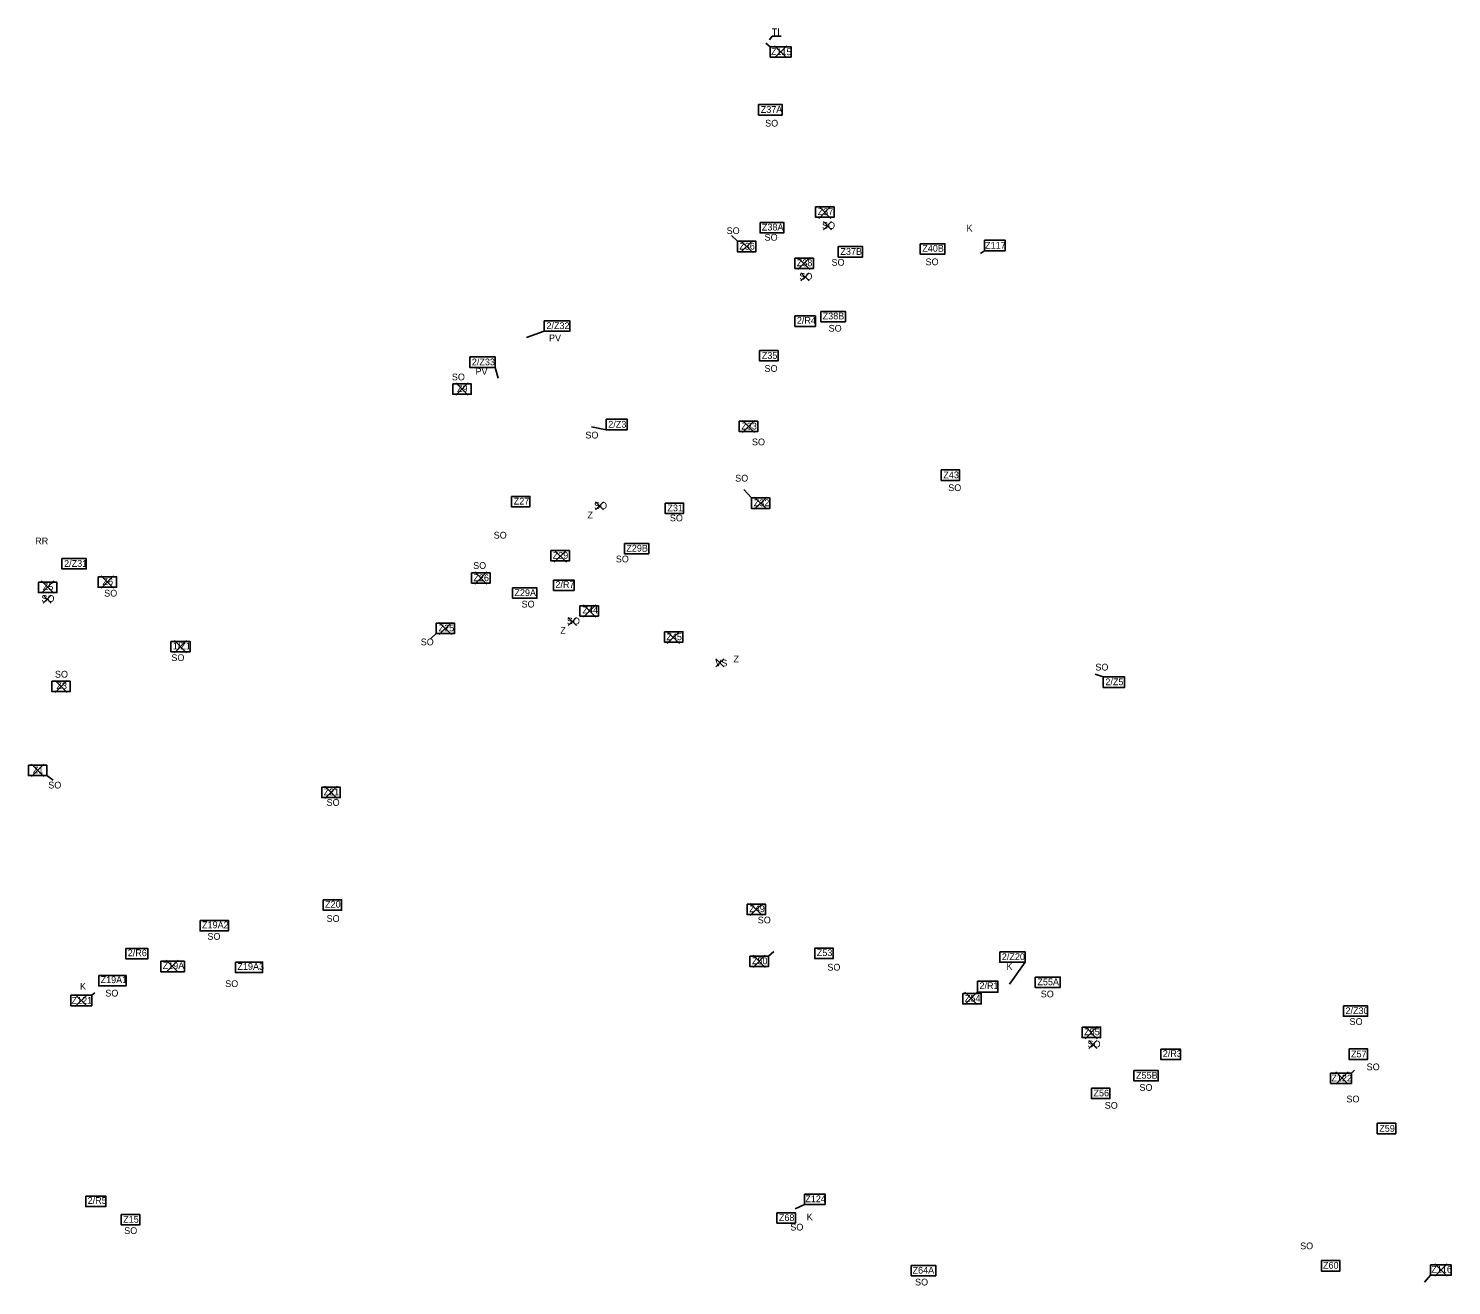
# Model space of a CAD drawing. Extents: x -443466 to -436070, y -1146578 to -1129775.
# Drawn here: x -442879 to -440772, y -1131637 to -1129775 of the extents above; entities that cross this region are included whole.
import ezdxf

# ---------------------------------------------------------------- set-up
doc = ezdxf.new("R2010")
doc.units = 0
for name, color, linetype in [('Vrstva 3', 7, 'Continuous'), ('Vrstva 4', 7, 'Continuous'), ('Vrstva 50', 7, 'Continuous'), ('Vrstva 8', 7, 'Continuous'), ('Vrstva 85', 7, 'Continuous')]:
    doc.layers.add(name, color=color, linetype=linetype)

msp = doc.modelspace()

# ---------------------------------------------------------------- linework, layer by layer
at = {"layer": 'Vrstva 3'}
for p, q in [((-441780.6, -1129802.1), (-441787.2, -1129796.7)), ((-441829.1, -1130090.3), (-441838, -1130081.7)), ((-442115.2, -1130223.5), (-442141.4, -1130232.8)), ((-442187.7, -1130277), (-442183.3, -1130293.2)), ((-442023.6, -1130369.3), (-442045.3, -1130365.1)), ((-441808.5, -1130470.4), (-441819.7, -1130457.7)), ((-442275.3, -1130671.3), (-442283.1, -1130678.3)), ((-441287.6, -1130735.5), (-441299.6, -1130731.1)), ((-442851.5, -1130881.4), (-442842.3, -1130888.4)), ((-441783.2, -1131148.9), (-441775.1, -1131141.9)), ((-441783.2, -1131148.9), (-441775.1, -1131141.9)), ((-441403.2, -1131157.9), (-441426.4, -1131190.3)), ((-440803, -1131621.5), (-440811.7, -1131631.9))]:
    msp.add_line(p, q, dxfattribs=at)
for points in [[(-441780.6, -1129802.1), (-441749.8, -1129802.1), (-441749.8, -1129817.5), (-441780.6, -1129817.5)], [(-441797.8, -1129887.9), (-441762.8, -1129887.9), (-441762.8, -1129903.3), (-441797.8, -1129903.3)], [(-441713.5, -1130039.3), (-441686.2, -1130039.3), (-441686.2, -1130054.7), (-441713.5, -1130054.7)], [(-441795.7, -1130062.4), (-441760.7, -1130062.4), (-441760.7, -1130077.8), (-441795.7, -1130077.8)], [(-441829.1, -1130090.3), (-441801.8, -1130090.3), (-441801.8, -1130105.7), (-441829.1, -1130105.7)], [(-441829.1, -1130090.3), (-441801.8, -1130090.3), (-441801.8, -1130105.7), (-441829.1, -1130105.7)], [(-441829.1, -1130090.3), (-441801.8, -1130090.3), (-441801.8, -1130105.7), (-441829.1, -1130105.7)], [(-441679.8, -1130098.2), (-441643.8, -1130098.2), (-441643.8, -1130113.6), (-441679.8, -1130113.6)], [(-441558.8, -1130093.8), (-441522, -1130093.8), (-441522, -1130109.2), (-441558.8, -1130109.2)], [(-441744, -1130115.3), (-441716.6, -1130115.3), (-441716.6, -1130130.7), (-441744, -1130130.7)], [(-442115.2, -1130208.1), (-442077.3, -1130208.1), (-442077.3, -1130223.5), (-442115.2, -1130223.5)], [(-441744, -1130200.9), (-441713.8, -1130200.9), (-441713.8, -1130216.3), (-441744, -1130216.3)], [(-441705.6, -1130194), (-441669.4, -1130194), (-441669.4, -1130209.4), (-441705.6, -1130209.4)], [(-441796.3, -1130252.1), (-441768.9, -1130252.1), (-441768.9, -1130267.5), (-441796.3, -1130267.5)], [(-442225.5, -1130261.6), (-442187.7, -1130261.6), (-442187.7, -1130277), (-442225.5, -1130277)], [(-442250.7, -1130301.4), (-442223.3, -1130301.4), (-442223.3, -1130316.8), (-442250.7, -1130316.8)], [(-442023.6, -1130353.9), (-441992.3, -1130353.9), (-441992.3, -1130369.3), (-442023.6, -1130369.3)], [(-441826.6, -1130356.8), (-441799.2, -1130356.8), (-441799.2, -1130372.2), (-441826.6, -1130372.2)], [(-441826.6, -1130356.8), (-441799.2, -1130356.8), (-441799.2, -1130372.2), (-441826.6, -1130372.2)], [(-441826.6, -1130356.8), (-441799.2, -1130356.8), (-441799.2, -1130372.2), (-441826.6, -1130372.2)], [(-441527.5, -1130428.9), (-441500.2, -1130428.9), (-441500.2, -1130444.3), (-441527.5, -1130444.3)], [(-441527.5, -1130428.9), (-441500.2, -1130428.9), (-441500.2, -1130444.3), (-441527.5, -1130444.3)], [(-442163.9, -1130468.1), (-442136.5, -1130468.1), (-442136.5, -1130483.5), (-442163.9, -1130483.5)], [(-441936.4, -1130477.9), (-441909, -1130477.9), (-441909, -1130493.3), (-441936.4, -1130493.3)], [(-441808.5, -1130470.4), (-441781.1, -1130470.4), (-441781.1, -1130485.8), (-441808.5, -1130485.8)], [(-442105.4, -1130548.2), (-442078, -1130548.2), (-442078, -1130563.6), (-442105.4, -1130563.6)], [(-442105.4, -1130548.2), (-442078, -1130548.2), (-442078, -1130563.6), (-442105.4, -1130563.6)], [(-442105.4, -1130548.2), (-442078, -1130548.2), (-442078, -1130563.6), (-442105.4, -1130563.6)], [(-441996.3, -1130537.6), (-441960.5, -1130537.6), (-441960.5, -1130553), (-441996.3, -1130553)], [(-442829.3, -1130560.1), (-442793.4, -1130560.1), (-442793.4, -1130575.5), (-442829.3, -1130575.5)], [(-442775.7, -1130587.1), (-442748.3, -1130587.1), (-442748.3, -1130602.5), (-442775.7, -1130602.5)], [(-442222.8, -1130581.2), (-442195.5, -1130581.2), (-442195.5, -1130596.5), (-442222.8, -1130596.5)], [(-442864.1, -1130595.1), (-442836.8, -1130595.1), (-442836.8, -1130610.4), (-442864.1, -1130610.4)], [(-442162.1, -1130603.5), (-442126, -1130603.5), (-442126, -1130618.9), (-442162.1, -1130618.9)], [(-442101.5, -1130592), (-442071, -1130592), (-442071, -1130607.4), (-442101.5, -1130607.4)], [(-442062.5, -1130629.9), (-442035.1, -1130629.9), (-442035.1, -1130645.2), (-442062.5, -1130645.2)], [(-442275.3, -1130655.9), (-442247.9, -1130655.9), (-442247.9, -1130671.3), (-442275.3, -1130671.3)], [(-441937.3, -1130668.5), (-441909.9, -1130668.5), (-441909.9, -1130683.9), (-441937.3, -1130683.9)], [(-442668, -1130682.7), (-442639.5, -1130682.7), (-442639.5, -1130698.1), (-442668, -1130698.1)], [(-441287.6, -1130735.5), (-441255.9, -1130735.5), (-441255.9, -1130750.9), (-441287.6, -1130750.9)], [(-442844.2, -1130741.8), (-442816.9, -1130741.8), (-442816.9, -1130757.2), (-442844.2, -1130757.2)], [(-442878.9, -1130866.1), (-442851.5, -1130866.1), (-442851.5, -1130881.4), (-442878.9, -1130881.4)], [(-442444.7, -1130898.7), (-442417.3, -1130898.7), (-442417.3, -1130914.1), (-442444.7, -1130914.1)], [(-442442.5, -1131065.5), (-442415.2, -1131065.5), (-442415.2, -1131080.9), (-442442.5, -1131080.9)], [(-441815, -1131072), (-441787.6, -1131072), (-441787.6, -1131087.4), (-441815, -1131087.4)], [(-442624.7, -1131096.1), (-442582.8, -1131096.1), (-442582.8, -1131111.5), (-442624.7, -1131111.5)], [(-442734.7, -1131137.5), (-442702.3, -1131137.5), (-442702.3, -1131152.9), (-442734.7, -1131152.9)], [(-441714.8, -1131137.1), (-441687.4, -1131137.1), (-441687.4, -1131152.5), (-441714.8, -1131152.5)], [(-442683.1, -1131156.5), (-442647.9, -1131156.5), (-442647.9, -1131171.9), (-442683.1, -1131171.9)], [(-442683.1, -1131156.5), (-442647.9, -1131156.5), (-442647.9, -1131171.9), (-442683.1, -1131171.9)], [(-442683.1, -1131156.5), (-442647.9, -1131156.5), (-442647.9, -1131171.9), (-442683.1, -1131171.9)], [(-442572.4, -1131157.8), (-442532.2, -1131157.8), (-442532.2, -1131173.2), (-442572.4, -1131173.2)], [(-441810.6, -1131148.9), (-441783.2, -1131148.9), (-441783.2, -1131164.3), (-441810.6, -1131164.3)], [(-441440.8, -1131142.5), (-441403.2, -1131142.5), (-441403.2, -1131157.9), (-441440.8, -1131157.9)], [(-442774.9, -1131177.5), (-442734.3, -1131177.5), (-442734.3, -1131192.9), (-442774.9, -1131192.9)], [(-441388.2, -1131179.9), (-441351.2, -1131179.9), (-441351.2, -1131195.3), (-441388.2, -1131195.3)], [(-441473.6, -1131186), (-441443.5, -1131186), (-441443.5, -1131202.5), (-441473.6, -1131202.5)], [(-441495.6, -1131204.2), (-441468.2, -1131204.2), (-441468.2, -1131219.6), (-441495.6, -1131219.6)], [(-440932, -1131222.5), (-440896.2, -1131222.5), (-440896.2, -1131237.9), (-440932, -1131237.9)], [(-441319, -1131254), (-441291.6, -1131254), (-441291.6, -1131269.4), (-441319, -1131269.4)], [(-441202.2, -1131286.7), (-441173.1, -1131286.7), (-441173.1, -1131302.1), (-441202.2, -1131302.1)], [(-440923.5, -1131286.4), (-440896.1, -1131286.4), (-440896.1, -1131301.8), (-440923.5, -1131301.8)], [(-441242.1, -1131318.4), (-441206.1, -1131318.4), (-441206.1, -1131333.8), (-441242.1, -1131333.8)], [(-441305.1, -1131344.5), (-441277.7, -1131344.5), (-441277.7, -1131359.9), (-441305.1, -1131359.9)], [(-440882, -1131396.5), (-440854.6, -1131396.5), (-440854.6, -1131411.9), (-440882, -1131411.9)], [(-442794, -1131504.3), (-442764.4, -1131504.3), (-442764.4, -1131519.7), (-442794, -1131519.7)], [(-442741.6, -1131531.5), (-442714.2, -1131531.5), (-442714.2, -1131546.9), (-442741.6, -1131546.9)], [(-441770.8, -1131528.9), (-441743.4, -1131528.9), (-441743.4, -1131544.3), (-441770.8, -1131544.3)], [(-440964.6, -1131599.8), (-440937.2, -1131599.8), (-440937.2, -1131615.2), (-440964.6, -1131615.2)], [(-441571.9, -1131606.9), (-441535.5, -1131606.9), (-441535.5, -1131622.3), (-441571.9, -1131622.3)], [(-440803, -1131606.1), (-440772.3, -1131606.1), (-440772.3, -1131621.5), (-440803, -1131621.5)]]:
    msp.add_lwpolyline(points, close=True, dxfattribs=at)
at = {"layer": 'Vrstva 4'}
msp.add_lwpolyline([(-441764.3, -1129786.7), (-441777.7, -1129786.7), (-441781.9, -1129791.9)], dxfattribs=at)
at = {"layer": 'Vrstva 50'}
for p, q in [((-441701.8, -1130073.2), (-441689.8, -1130061.2)), ((-441701.8, -1130061.2), (-441689.8, -1130073.2)), ((-441735.1, -1130148.9), (-441723.1, -1130136.9)), ((-441735.1, -1130136.9), (-441723.1, -1130148.9)), ((-442039.4, -1130488.2), (-442027.4, -1130476.2)), ((-442039.4, -1130476.2), (-442027.4, -1130488.2)), ((-442039.4, -1130488.2), (-442027.4, -1130476.2)), ((-442039.4, -1130476.2), (-442027.4, -1130488.2)), ((-442079.6, -1130659.2), (-442067.6, -1130647.2)), ((-442079.6, -1130647.2), (-442067.6, -1130659.2)), ((-442079.6, -1130659.2), (-442067.6, -1130647.2)), ((-442079.6, -1130647.2), (-442067.6, -1130659.2)), ((-441861.1, -1130720.7), (-441849.1, -1130708.7)), ((-441861.1, -1130708.7), (-441849.1, -1130720.7)), ((-441309, -1131285.9), (-441297, -1131273.9)), ((-441309, -1131273.9), (-441297, -1131285.9))]:
    msp.add_line(p, q, dxfattribs=at)
at = {"layer": 'Vrstva 8'}
for p, q in [((-441463.6, -1130104.2), (-441469.4, -1130108.5)), ((-442785.3, -1131206.9), (-442780.8, -1131203.4)), ((-440920.2, -1131322), (-440915.5, -1131317.9)), ((-441730.1, -1131516.6), (-441743.7, -1131522.9))]:
    msp.add_line(p, q, dxfattribs=at)
for points in [[(-441463.6, -1130088.8), (-441432.8, -1130088.8), (-441432.8, -1130104.2), (-441463.6, -1130104.2)], [(-442816.1, -1131206.9), (-442785.3, -1131206.9), (-442785.3, -1131222.3), (-442816.1, -1131222.3)], [(-440951, -1131322), (-440920.2, -1131322), (-440920.2, -1131337.4), (-440951, -1131337.4)], [(-441730.1, -1131501.3), (-441699.3, -1131501.3), (-441699.3, -1131516.7), (-441730.1, -1131516.7)]]:
    msp.add_lwpolyline(points, close=True, dxfattribs=at)
at = {"layer": 'Vrstva 85'}
for p, q in [((-441774.2, -1129800.8), (-441756.2, -1129818.8)), ((-441756.2, -1129800.8), (-441774.2, -1129818.8)), ((-441708.9, -1130038.3), (-441690.9, -1130056.3)), ((-441690.9, -1130038.3), (-441708.9, -1130056.3)), ((-441824.5, -1130089), (-441806.5, -1130107)), ((-441806.5, -1130089), (-441824.5, -1130107)), ((-441824.5, -1130089), (-441806.5, -1130107)), ((-441806.5, -1130089), (-441824.5, -1130107)), ((-441739.8, -1130114.1), (-441721.8, -1130132.1)), ((-441721.8, -1130114.1), (-441739.8, -1130132.1)), ((-442246, -1130300.1), (-442228, -1130318.1)), ((-442228, -1130300.1), (-442246, -1130318.1)), ((-442246, -1130300.1), (-442228, -1130318.1)), ((-442228, -1130300.1), (-442246, -1130318.1)), ((-441821.9, -1130355.5), (-441803.9, -1130373.5)), ((-441803.9, -1130355.5), (-441821.9, -1130373.5)), ((-441803.8, -1130469.1), (-441785.8, -1130487.1)), ((-441785.8, -1130469.1), (-441803.8, -1130487.1)), ((-442100.4, -1130547.5), (-442082.4, -1130565.5)), ((-442082.4, -1130547.5), (-442100.4, -1130565.5)), ((-442771.1, -1130585.9), (-442753.1, -1130603.9)), ((-442753.1, -1130585.9), (-442771.1, -1130603.9)), ((-442218.1, -1130579.8), (-442200.1, -1130597.8)), ((-442200.1, -1130579.8), (-442218.1, -1130597.8)), ((-442218.1, -1130579.8), (-442200.1, -1130597.8)), ((-442200.1, -1130579.8), (-442218.1, -1130597.8)), ((-442859.5, -1130593.2), (-442841.5, -1130611.2)), ((-442841.5, -1130593.2), (-442859.5, -1130611.2)), ((-442857.1, -1130626.1), (-442845.1, -1130614.1)), ((-442857.1, -1130614.1), (-442845.1, -1130626.1)), ((-442057, -1130628.7), (-442039, -1130646.7)), ((-442039, -1130628.7), (-442057, -1130646.7)), ((-442270.6, -1130654.6), (-442252.6, -1130672.6)), ((-442252.6, -1130654.6), (-442270.6, -1130672.6)), ((-441933, -1130668), (-441915, -1130686)), ((-441915, -1130668), (-441933, -1130686)), ((-442662.8, -1130681.5), (-442644.8, -1130699.5)), ((-442644.8, -1130681.5), (-442662.8, -1130699.5)), ((-442839.5, -1130740.5), (-442821.5, -1130758.5)), ((-442821.5, -1130740.5), (-442839.5, -1130758.5)), ((-442874.2, -1130864.8), (-442856.2, -1130882.8)), ((-442856.2, -1130864.8), (-442874.2, -1130882.8)), ((-442440, -1130897.4), (-442422, -1130915.4)), ((-442422, -1130897.4), (-442440, -1130915.4)), ((-441810.3, -1131070.7), (-441792.3, -1131088.7)), ((-441792.3, -1131070.7), (-441810.3, -1131088.7)), ((-442675.1, -1131154.7), (-442657.1, -1131172.7)), ((-442657.1, -1131154.7), (-442675.1, -1131172.7)), ((-441805.9, -1131147.6), (-441787.9, -1131165.6)), ((-441787.9, -1131147.6), (-441805.9, -1131165.6)), ((-442809.7, -1131205.6), (-442791.7, -1131223.6)), ((-442791.7, -1131205.6), (-442809.7, -1131223.6)), ((-442809.7, -1131205.6), (-442791.7, -1131223.6)), ((-442791.7, -1131205.6), (-442809.7, -1131223.6)), ((-441492.3, -1131202.4), (-441474.3, -1131220.4)), ((-441474.3, -1131202.4), (-441492.3, -1131220.4)), ((-441314.4, -1131253.2), (-441296.4, -1131271.2)), ((-441296.4, -1131253.2), (-441314.4, -1131271.2)), ((-440943.1, -1131320.4), (-440925.1, -1131338.4)), ((-440925.1, -1131320.4), (-440943.1, -1131338.4)), ((-440796.6, -1131604.8), (-440778.6, -1131622.8)), ((-440778.6, -1131604.8), (-440796.6, -1131622.8))]:
    msp.add_line(p, q, dxfattribs=at)

# ---------------------------------------------------------------- texts
at = {"layer": 'Vrstva 3'}
for s, p in [('Z115', (-441779.6, -1129814.6)), ('Z37A', (-441794.7, -1129900.1)), ('Z37', (-441794.7, -1129900.1)), ('Z37', (-441710.4, -1130051.5)), ('Z38A', (-441793, -1130074.3)), ('Z36', (-441826.5, -1130102.5)), ('Z36', (-441826.5, -1130102.5)), ('Z36', (-441826.5, -1130102.5)), ('Z37B', (-441676.7, -1130110.4)), ('Z37', (-441676.7, -1130110.4)), ('Z40B', (-441555.5, -1130105.7)), ('Z38', (-441741.3, -1130127.2)), ('2/Z32', (-442112, -1130220.3)), ('2/R4', (-441741.2, -1130212.5)), ('Z38B', (-441703, -1130205.9)), ('2/Z33', (-442222.4, -1130273.9)), ('Z35', (-441793.1, -1130264.3)), ('Z9', (-442244.4, -1130313.5)), ('2/Z3', (-442020.4, -1130366.2)), ('Z33', (-441823.4, -1130369)), ('Z33', (-441823.4, -1130369)), ('Z33', (-441823.4, -1130369)), ('Z43', (-441524.3, -1130441.2)), ('Z43', (-441524.3, -1130441.2)), ('Z27', (-442160.4, -1130480.1)), ('Z31', (-441932.9, -1130490.1)), ('Z32', (-441805, -1130482.6)), ('Z29B', (-441993.7, -1130549.8)), ('Z29', (-441993.7, -1130549.8)), ('Z29', (-441993.7, -1130549.8)), ('2/Z31', (-442826.1, -1130572.4)), ('Z29', (-442102.7, -1130560.4)), ('Z29', (-442102.7, -1130560.4)), ('Z29', (-442102.7, -1130560.4)), ('Z6', (-442769.2, -1130599.2)), ('Z26', (-442220.1, -1130593.6)), ('Z5', (-442857.7, -1130606.9)), ('Z29A', (-442159.4, -1130615.7)), ('Z29', (-442159.4, -1130615.7)), ('Z29', (-442159.4, -1130615.7)), ('2/R7', (-442098.7, -1130603.6)), ('Z44', (-442058.6, -1130641.4)), ('Z25', (-442271.7, -1130668)), ('Z45', (-441934.4, -1130681)), ('1/Z1', (-442665.2, -1130694.6)), ('2/Z5', (-441284.4, -1130747.7)), ('Z3', (-442837.5, -1130753.5)), ('Z1', (-442872.3, -1130878.1)), ('Z21', (-442441.8, -1130910.7)), ('Z20', (-442439.7, -1131077)), ('Z49', (-441811.7, -1131083.8)), ('Z19A', (-442621.9, -1131107.6)), ('Z19A', (-442621.9, -1131107.6)), ('Z19A2', (-442621.9, -1131107.6)), ('2/R6', (-442731.9, -1131149)), ('Z19A', (-442680.2, -1131168)), ('Z19A', (-442680.2, -1131168)), ('Z19A', (-442680.2, -1131168)), ('Z19A', (-442569.5, -1131169.2)), ('Z19A', (-442569.5, -1131169.2)), ('Z19A3', (-442569.5, -1131169.2)), ('Z50', (-441807.7, -1131160.9)), ('Z53', (-441711.7, -1131148.8)), ('2/Z20', (-441437.7, -1131154.7)), ('Z19A', (-442772.1, -1131188.9)), ('Z19A', (-442772.1, -1131188.9)), ('Z19A1', (-442772.1, -1131188.9)), ('2/R1', (-441470.8, -1131197.6)), ('Z55A', (-441385.1, -1131192)), ('Z54', (-441492.5, -1131216.4)), ('2/Z30', (-440928.9, -1131234.7)), ('Z55', (-441315.9, -1131266)), ('2/R3', (-441199.4, -1131298.2)), ('Z57', (-440920.7, -1131298.8)), ('Z55B', (-441239, -1131330.4)), ('Z56', (-441302, -1131356.6)), ('Z59', (-440878.9, -1131409)), ('2/R5', (-442791.2, -1131515.8)), ('Z15', (-442738.6, -1131543.7)), ('Z68', (-441767.8, -1131541.2)), ('Z60', (-440962.2, -1131611.7)), ('Z64A', (-441569.9, -1131619.1)), ('Z64', (-441569.9, -1131619.1)), ('Z116', (-440801.8, -1131617.8))]:
    msp.add_text(s, height=10, dxfattribs=at).set_placement(p)
at = {"layer": 'Vrstva 4'}
for s, p in [('TI', (-441778.4, -1129785.1)), ('SO', (-441788.2, -1129920.4)), ('SO', (-441788.2, -1129920.4)), ('SO', (-441703.9, -1130071.8)), ('SO', (-441845.2, -1130079.6)), ('SO', (-441789, -1130089.4)), ('K', (-441490.1, -1130075.8)), ('SO', (-441689.9, -1130126.5)), ('SO', (-441550.7, -1130125.7)), ('SO', (-441737.5, -1130147.2)), ('PV', (-442108.2, -1130238.4)), ('SO', (-441694.2, -1130224.1)), ('SO', (-441789.1, -1130283.6)), ('SO', (-442252, -1130296.2)), ('PV', (-442217, -1130288)), ('SO', (-442054.3, -1130382.3)), ('SO', (-442054.3, -1130382.3)), ('SO', (-441807.7, -1130392.4)), ('SO', (-441832.5, -1130446.1)), ('SO', (-441517.1, -1130460.2)), ('SO', (-441517.1, -1130460.2)), ('SO', (-442041.5, -1130486.7)), ('Z', (-442051.2, -1130500.5)), ('SO', (-441929.2, -1130505)), ('SO', (-442190.1, -1130530.5)), ('RR', (-442868.9, -1130539)), ('SO', (-442220.5, -1130575.4)), ('SO', (-442009.3, -1130565.7)), ('SO', (-442766.8, -1130616.4)), ('SO', (-442859.7, -1130624.2)), ('SO', (-442148.8, -1130632.6)), ('SO', (-442081.7, -1130657.6)), ('Z', (-442091.5, -1130671.4)), ('SO', (-442298.1, -1130688.6)), ('SO', (-442667.3, -1130711.9)), ('VS', (-441862, -1130719.8)), ('Z', (-441835, -1130713.7)), ('SO', (-441299.2, -1130725.9)), ('SO', (-442839.7, -1130736.4)), ('SO', (-442849.6, -1130900.6)), ('SO', (-442437.5, -1130926.3)), ('SO', (-442437.5, -1131098.2)), ('SO', (-441799.1, -1131100.4)), ('SO', (-442613.9, -1131124.7)), ('K', (-441430.9, -1131169.2)), ('SO', (-441696, -1131170.3)), ('K', (-442802.6, -1131198.5)), ('SO', (-442765.1, -1131208.7)), ('SO', (-442765.1, -1131208.7)), ('SO', (-442765.1, -1131208.7)), ('SO', (-442587.6, -1131194.7)), ('SO', (-441380.1, -1131209.9)), ('SO', (-440922.9, -1131250.8)), ('SO', (-441310.9, -1131284)), ('SO', (-440897.6, -1131317.9)), ('SO', (-441234, -1131348.4)), ('SO', (-441285.4, -1131374.9)), ('SO', (-440927.5, -1131365.5)), ('K', (-441726.6, -1131540.1)), ('SO', (-442737.1, -1131560.4)), ('SO', (-441750.9, -1131555.2)), ('SO', (-440996.1, -1131583)), ('SO', (-441566.2, -1131636.6))]:
    msp.add_text(s, height=10, dxfattribs=at).set_placement(p)
at = {"layer": 'Vrstva 8'}
for s, p in [('Z117', (-441462.5, -1130101.2)), ('Z121', (-442815.1, -1131219.3)), ('Z122', (-440949.9, -1131334.5)), ('Z124', (-441728.7, -1131513.3))]:
    msp.add_text(s, height=10, dxfattribs=at).set_placement(p)

doc.saveas('drawing.dxf')
